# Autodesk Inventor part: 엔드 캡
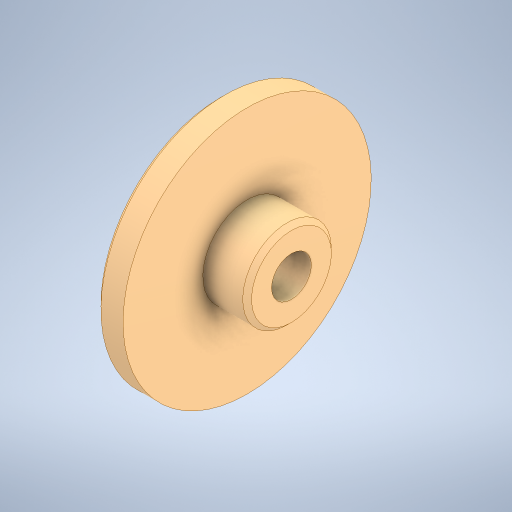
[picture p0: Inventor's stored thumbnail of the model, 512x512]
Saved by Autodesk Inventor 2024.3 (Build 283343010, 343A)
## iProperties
Created: 2025-11
Part Number: 엔드 캡
Material: 강철, 연강
Document SubType Name: Modeling
Designer: PC2-15
Density: 7.85 g/cm^3
Appearance: 기본값
Author: jhkim
Sending System: Autodesk Inventor 2026
Preprocessor: ST-DEVELOPER v20.1
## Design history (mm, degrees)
node "엔드 캡1"
node "솔리드2"
node "솔리드1"
